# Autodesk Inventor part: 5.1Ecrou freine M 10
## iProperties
Created: 2011-01
Part Number: 5.1Ecrou freine M 10
Document SubType Name: Modeling
Designer: eric
Density: 1 g/cm^3
Mass: 1.8546 g
Surface Area: 12.1018 cm^2
Volume: 1.8546 cm^3
Author: eric
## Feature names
1. Base1
